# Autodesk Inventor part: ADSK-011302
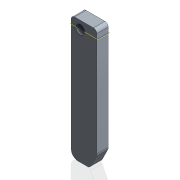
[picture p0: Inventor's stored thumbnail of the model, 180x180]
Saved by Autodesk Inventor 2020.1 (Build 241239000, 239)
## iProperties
Created: 1999-11
Part Number: ADSK-011302
Material: Pearson Aluminium
Description: PLT-02,FA,CP,07,017,085,C9,FINGER,FLIGHT
Document SubType Name: Modeling
Designer: sspink
Density: 2.71 g/cm^3
Appearance: Pearson-Aluminum
Mass: 504.225 g
Surface Area: 297.647 cm^2
Volume: 186.061 cm^3
Control State: 0
Checked Out: False
Last Check In By: sspink
Last Check In Date: 1999-12-16
Master: False
Shininess: 35.0
Length Units: 11269
Angle Units: 11279
Time Units: 11290
Mass Units: 11283
Length Display Precision: 3
Angle Display Precision: 2
Compacted: True
Material Desc: FLAT,ALUM,0.75 X 2.00
Cutlength: 8.5
Material_number: A087029
Dimensions: 45x216x20 mm
Mass: 0,504 kg
DocNumber: ADSK-011302.ipt
Folder: 01 - Themengebiete\Simplification\01 - Packaging machine\
VDS_Category: 3D Komponenten
Density: 2.71
Volumn: 174.5522452204986
Area: 289.5157328939588
PropertySet Name: Model Information
Author: sspink
Revision Number: -
Title: PLT-02,FA,CP,07,017,085,C9,FINGER,FLIGHT
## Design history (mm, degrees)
node "Solide1"
  node "Extrusion1" dims "d4" = 20, "d5" = 0
  node "Hole1" dims "d8" = 16, "d9" = 9.525, "d10" = 6.35, "d11" = 60 deg, "d12" = 19.05, "d13" = 118 deg, "d28" = 6
  node "Fillet2" dims "d15" = 12
  node "Extrusion2" dims "d18" = 19.05, "d19" = 0
  node "Hole2" dims "d20" = 4.134, "d21" = 9.525, "d22" = 6.35, "d23" = 60 deg, "d24" = 19.05, "d25" = 118 deg, "d31" = 10
  node "Fillet3" dims "d26" = 6
  node "Fillet4" dims "d27" = 12
sketch "Sketch1"
  geometry: L1 (22.5, 108)-(-22.5, 108); L2 (-22.5, 108)-(-22.5, -108); L3 (-22.5, -108)-(10, -108); L4 (22.5, -83)-(22.5, 108); L5 (22.5, -83)-(10, -108); 3 further points
  constraints: 10 end point, 2 midpoint, 2 parallel, 1 horizontal, 1 horizontal alignment, 1 perpendicular, 1 vertical alignment
  dimensions: "d0" = 45 distance of L1.start L1.end; "d1" = 216 distance of L1.end L2.end; "d2" = 12.5 distance from line of L4 L3.end; "d3" = 25 distance from line of L3 L4.start
sketch "Sketch2"
  geometry: L1 (-22.5, 108)-(22.5, 108) reference; L2 (-22.5, -108)-(-22.5, 108) reference; 1 further point
  dimensions: "d6" = 14 distance from line of point (-6.5, 94) L1; "d7" = 16 distance from line of point (-6.5, 94) L2
workplane "Arbeitsebene1"
sketch "Sketch3"
  geometry: L1 (-6.5, 94)-(-15.5, 94); L2 (-15.5, 96.5)-(-14.099, 96.5); L3 (-15.5, 91.5)-(-14.099, 91.5); L4 (-15.5, 96.5)-(-15.5, 91.5); A1 r 8 centre (-6.5, 94) between (-14.099, 96.5) and (-14.099, 91.5) reference
  constraints: 8 end point, 2 horizontal, 2 point on circle, 1 midpoint, 1 parallel, 1 perpendicular
  dimensions: "d29" = 5 distance of L2.start L3.start; "d30" = 9 distance from line of L1.start L4
sketch "Sketch4"
  geometry: L1 (91.5, -20)-(96.5, -20) reference; L2 (108, 0)-(108, -20) reference; 3 further points
  constraints: 2 midpoint, 1 horizontal alignment, 1 vertical alignment
node "Corps solides"
node "Corps surfaciques"
